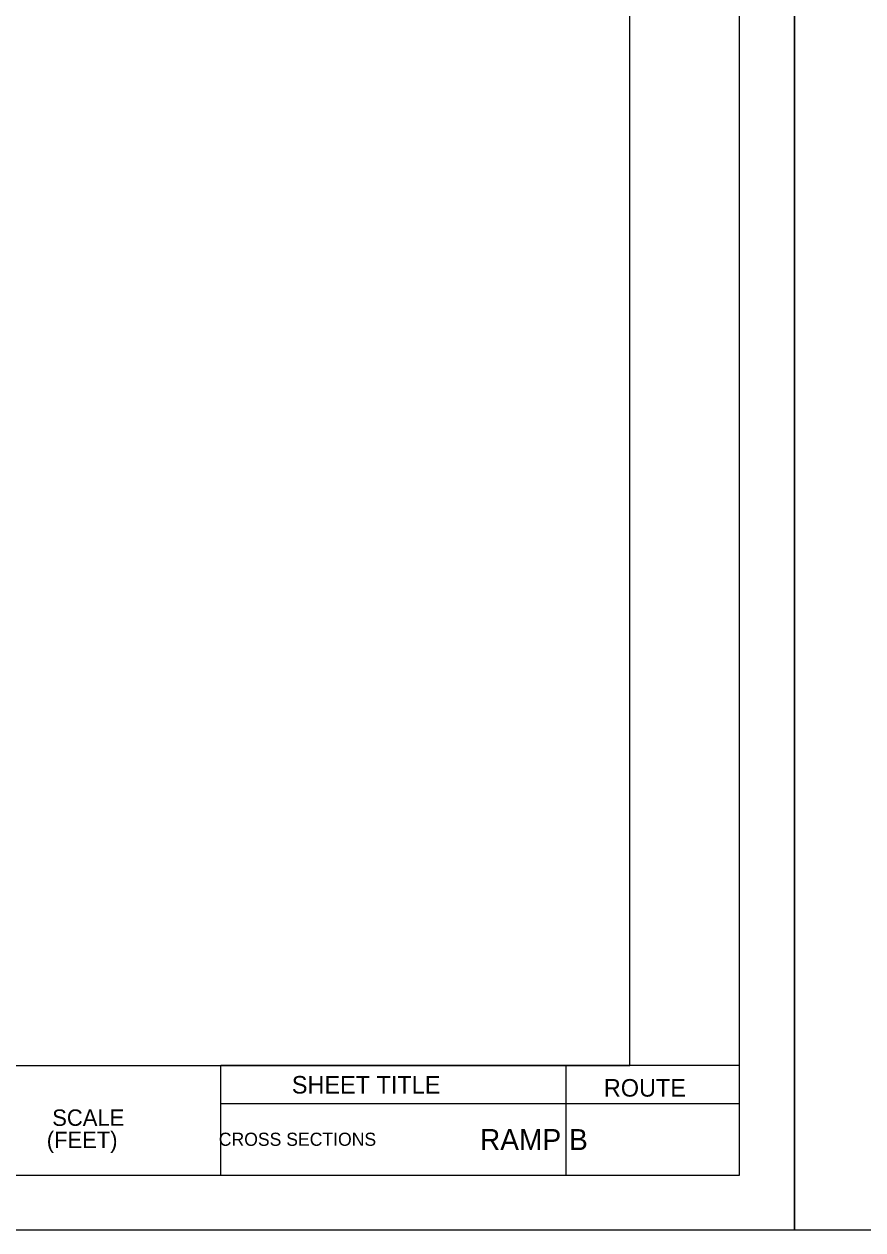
# Model space of a CAD drawing. Extents: x 1797478 to 1805176, y 246529 to 250952.
# Drawn here: x 1802385.7 to 1802462.3, y 250064.4 to 250174.4 of the extents above; entities that cross this region are included whole.
import ezdxf

# ---------------------------------------------------------------- set-up
doc = ezdxf.new("R2010")
doc.units = 0
for name, color, linetype in [('ANNO-SHT', 7, 'Continuous'), ('ANNO-SYMB', 7, 'Continuous'), ('ANNO-TXT', 7, 'Continuous'), ('Level 6', 7, 'Continuous'), ('Level 62', 7, 'Continuous'), ('SHT-BDR', 7, 'Continuous'), ('SHT-BNDRY', 7, 'Continuous')]:
    doc.layers.add(name, color=color, linetype=linetype)

msp = doc.modelspace()

# ---------------------------------------------------------------- linework, layer by layer
at = {"layer": 'ANNO-TXT'}
for p, q in [((1802403.66, 250075.96), (1802435.19, 250075.96)), ((1802435.19, 250075.96), (1802451, 250075.96))]:
    msp.add_line(p, q, dxfattribs=at)
at = {"layer": 'Level 6'}
msp.add_line((1802451, 250079.43), (1802403.66, 250079.43), dxfattribs=at)
at = {"layer": 'Level 62'}
for points in [[(1802116, 250064.42), (1802456, 250064.42), (1802456, 250284.42), (1802116, 250284.42)], [(1802456, 250064.42), (1802796, 250064.42), (1802796, 250284.42), (1802456, 250284.42)]]:
    msp.add_lwpolyline(points, close=True, dxfattribs=at)
at = {"layer": 'SHT-BDR'}
msp.add_lwpolyline([(1802141, 250079.43), (1802441, 250079.43), (1802441, 250269.43), (1802141, 250269.43)], close=True, dxfattribs=at)
at = {"layer": 'SHT-BNDRY'}
for p, q in [((1802403.66, 250069.42), (1802403.66, 250079.43)), ((1802435.19, 250069.42), (1802435.19, 250079.43))]:
    msp.add_line(p, q, dxfattribs=at)
msp.add_lwpolyline([(1802128.5, 250069.42), (1802451, 250069.42), (1802451, 250279.42), (1802128.5, 250279.42)], close=True, dxfattribs=at)

# ---------------------------------------------------------------- texts
at = {"layer": 'ANNO-SHT'}
for s, height, p in [('          CROSS SECTIONS          ', 1.2, (1802399.03, 250072.09)), ('       RAMP B       ', 1.92, (1802422.32, 250071.7))]:
    msp.add_text(s, height=height, rotation=360, dxfattribs=at).set_placement(p)
at = {"layer": 'ANNO-SYMB'}
for s, p in [('SCALE', (1802388.29, 250073.91)), ('(FEET)', (1802387.79, 250071.88))]:
    msp.add_text(s, height=1.499, rotation=0.0572, dxfattribs=at).set_placement(p)
at = {"layer": 'ANNO-TXT'}
for s, p in [('SHEET TITLE', (1802410.15, 250076.86)), ('ROUTE', (1802438.62, 250076.58))]:
    msp.add_text(s, height=1.6, dxfattribs=at).set_placement(p)

doc.saveas('drawing.dxf')
